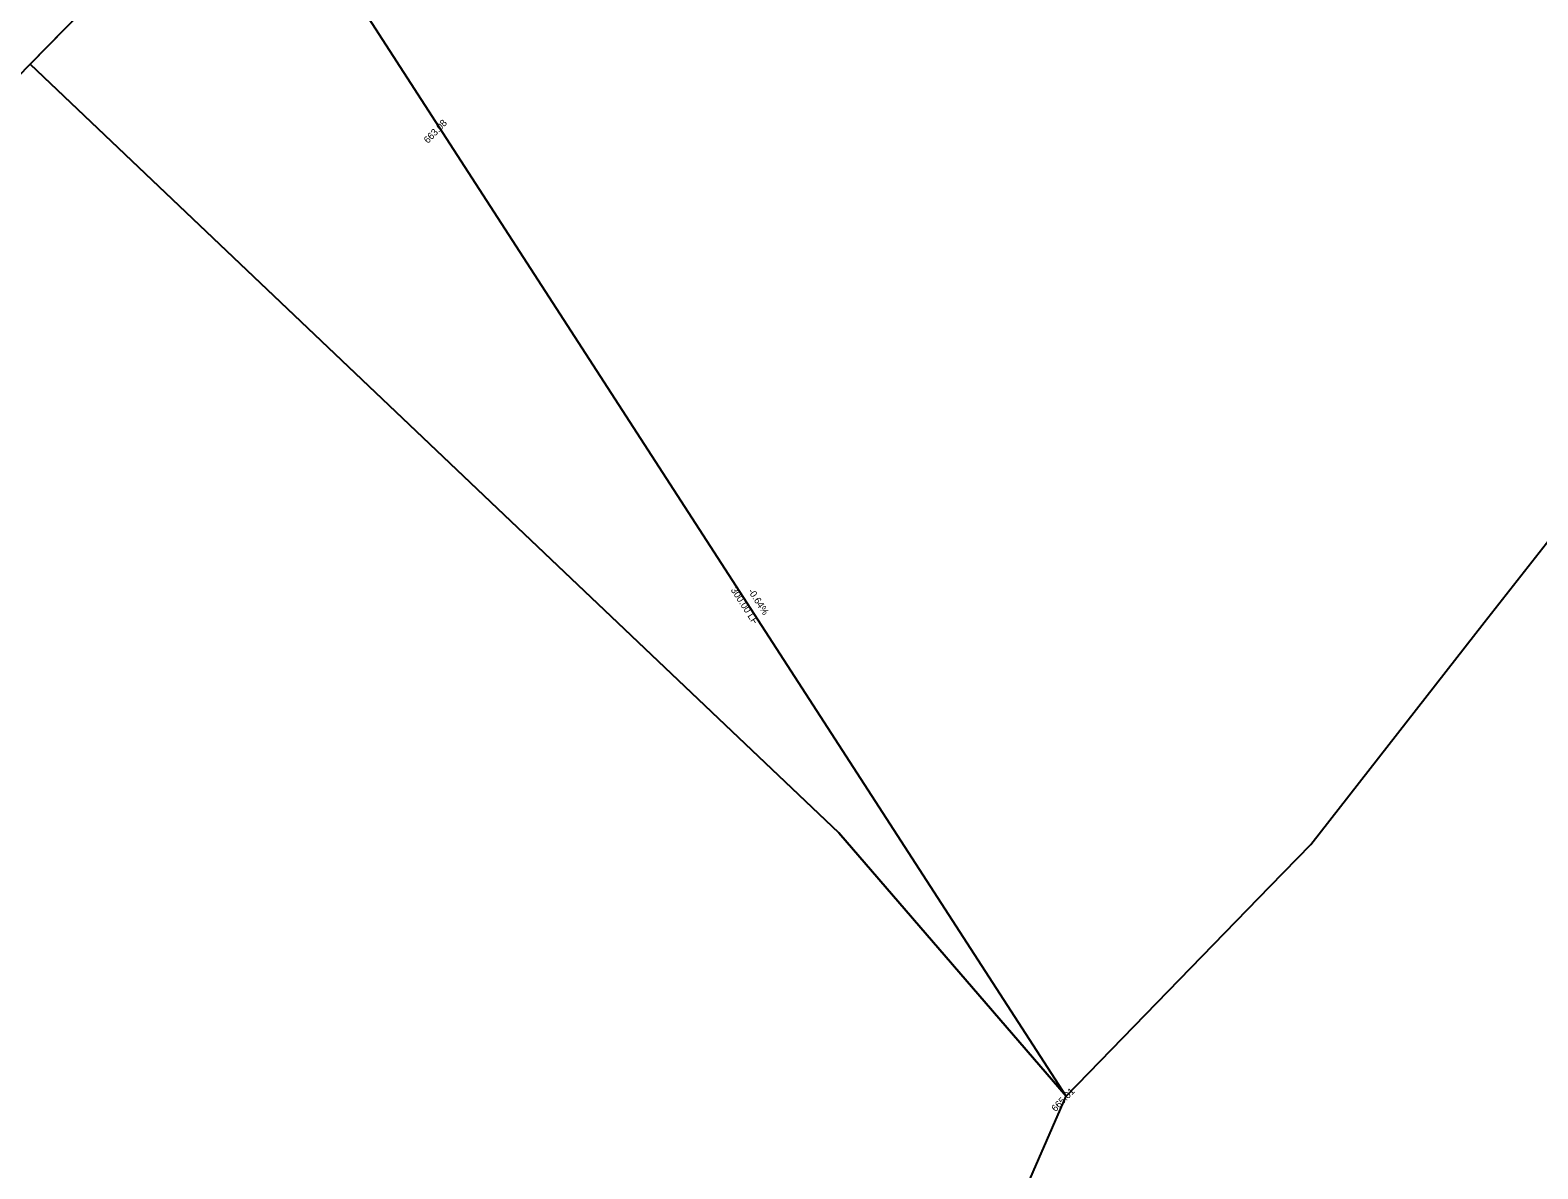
# Model space of a CAD drawing. Extents: x 2252703 to 2264864, y 13787568 to 13790989.
# Drawn here: x 2253219.9 to 2253611.7, y 13788691.8 to 13788987.8 of the extents above; entities that cross this region are included whole.
import ezdxf

# ---------------------------------------------------------------- set-up
doc = ezdxf.new("R2010")
doc.units = 0
for name, color, linetype in [('D_DRAIN_NOTES_1', 7, 'Continuous'), ('D_DRN_AREA_X', 7, 'Continuous'), ('D_DRN_SHALLOW_CONC_FLOW', 7, 'Continuous'), ('D_DRN_SHEET_FLOW', 7, 'Continuous')]:
    doc.layers.add(name, color=color, linetype=linetype)

msp = doc.modelspace()

# ---------------------------------------------------------------- linework, layer by layer
at = {"layer": 'D_DRN_AREA_X'}
for p, q in [((2253597.73, 13788833.83), (2253772.99, 13789058.01)), ((2253219.88, 13788979.03), (2253238.61, 13788998.19)), ((2253219.88, 13788979.03), (2253343.04, 13788861.89)), ((2253343.04, 13788861.89), (2253219.88, 13788979.03)), ((2253343.04, 13788861.89), (2253430.01, 13788779.17)), ((2253430.01, 13788779.17), (2253343.04, 13788861.89)), ((2253552.66, 13788776.19), (2253597.73, 13788833.83)), ((2253430.01, 13788779.17), (2253489.08, 13788710.7)), ((2253489.08, 13788710.7), (2253430.01, 13788779.17)), ((2253542.12, 13788765.33), (2253552.66, 13788776.19)), ((2253489.08, 13788710.7), (2253542.12, 13788765.33)), ((2253326.56, 13788337.69), (2253489.08, 13788710.7))]:
    msp.add_line(p, q, dxfattribs=at)
for points in [[(2253498.79, 13789264.43), (2253238.61, 13788998.19), (2253219.88, 13788979.03)], [(2253219.88, 13788979.03), (2253206.62, 13788965.47), (2253167.13, 13788925.05), (2253127.32, 13788884.07), (2253097.55, 13788852.82), (2253095.25, 13788850.52), (2253094.09, 13788849.37)]]:
    msp.add_lwpolyline(points, dxfattribs=at)
at = {"layer": 'D_DRN_SHALLOW_CONC_FLOW'}
msp.add_line((2253326.2, 13788962.63), (2253282.21, 13789030.65), dxfattribs=at)
msp.add_line((2253326.2, 13788962.63), (2253282.21, 13789030.65), dxfattribs=at)
at = {"layer": 'D_DRN_SHEET_FLOW'}
msp.add_line((2253489.08, 13788710.7), (2253326.2, 13788962.63), dxfattribs=at)
msp.add_line((2253489.08, 13788710.7), (2253326.2, 13788962.63), dxfattribs=at)

# ---------------------------------------------------------------- texts
at = {"layer": 'D_DRAIN_NOTES_1'}
for s, p in [('663.08', (2253323.25, 13788958.27)), ('665.01', (2253486.34, 13788706.55))]:
    msp.add_text(s, height=1.8, rotation=46.1117, dxfattribs=at).set_placement(p)
at = {"layer": 'D_DRN_SHEET_FLOW'}
for s, p in [('300.00 LF', (2253401.85, 13788842.31)), ('-0.64%', (2253406.32, 13788842.02))]:
    msp.add_text(s, height=1.8, rotation=302.8853, dxfattribs=at).set_placement(p)

doc.saveas('drawing.dxf')
